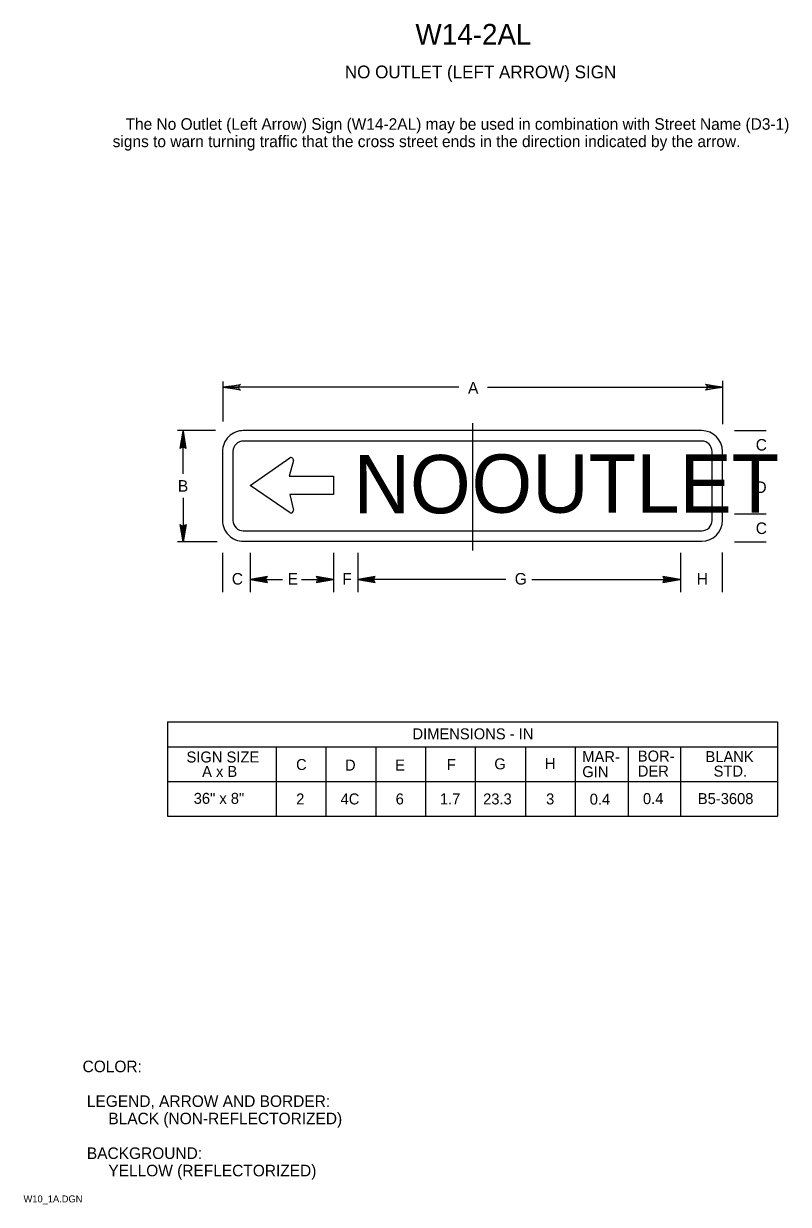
# Model space of a CAD drawing. Extents: x 0.013 to 0.178, y 0.004 to 0.259.
import ezdxf

# ---------------------------------------------------------------- set-up
doc = ezdxf.new("R2010")
doc.units = 0
for name, color, linetype in [('1', 7, 'Continuous'), ('2', 7, 'Continuous'), ('3', 7, 'Continuous')]:
    doc.layers.add(name, color=color, linetype=linetype)

# ---------------------------------------------------------------- blocks, each defined once
blk = doc.blocks.new('RARROW')
at = {"layer": '3'}
for p, q in [((-2.156, 0.28500000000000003), (-2.2665, 0.384625)), ((-2.2665, 0.384625), (0, 0)), ((0, 0), (-2.2665, -0.379125)), ((-2.156, 0.28500000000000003), (-2.075625, 0.12075)), ((0, 0), (-2.156, 0.28500000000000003)), ((-2.14975, -0.2705), (0, 0)), ((-2.075625, 0.12075), (0, 0)), ((0, 0), (-2.074, -0.108)), ((-2.2665, -0.379125), (-2.14975, -0.2705)), ((-2.074, -0.108), (-2.14975, -0.2705))]:
    blk.add_line(p, q, dxfattribs=at)

msp = doc.modelspace()

# ---------------------------------------------------------------- linework, layer by layer
at = {"layer": '1'}
msp.add_line((0.10961895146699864, 0.17275000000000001), (0.10961895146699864, 0.14523299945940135), dxfattribs=at)
at = {"layer": '3'}
for p, q in [((0.055725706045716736, 0.173125), (0.055725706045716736, 0.18174713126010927)), ((0.16373811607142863, 0.1725172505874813), (0.16373811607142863, 0.18188938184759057)), ((0.1066937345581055, 0.18049713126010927), (0.05576086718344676, 0.18049713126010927)), ((0.11287659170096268, 0.18049713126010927), (0.16372946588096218, 0.18049713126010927)), ((0.05409428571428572, 0.17112213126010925), (0.04588586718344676, 0.17112213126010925)), ((0.04713586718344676, 0.16175542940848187), (0.04713586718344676, 0.17112213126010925)), ((0.15914361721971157, 0.171125), (0.06009428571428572, 0.171125)), ((0.16620796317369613, 0.171125), (0.17308296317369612, 0.171125)), ((0.15914361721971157, 0.168875), (0.06009428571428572, 0.168875)), ((0.05559428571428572, 0.166625), (0.05559428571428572, 0.15172487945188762)), ((0.057844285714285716, 0.166625), (0.057844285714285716, 0.15172487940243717)), ((0.16139361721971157, 0.15172874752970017), (0.16139361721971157, 0.16662886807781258)), ((0.16364361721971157, 0.15172874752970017), (0.16364361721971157, 0.16662886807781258)), ((0.06159228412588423, 0.15924376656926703), (0.07016160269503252, 0.16523741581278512)), ((0.07091637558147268, 0.16466019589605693), (0.07003009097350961, 0.16127193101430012)), ((0.16620796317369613, 0.165125), (0.17308296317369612, 0.165125)), ((0.07003009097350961, 0.16127193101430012), (0.07958125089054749, 0.16127193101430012)), ((0.07958125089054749, 0.1612719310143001), (0.07958125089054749, 0.15730317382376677)), ((0.07020559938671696, 0.1533827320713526), (0.06159228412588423, 0.15924376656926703)), ((0.04713586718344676, 0.15662658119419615), (0.04713586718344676, 0.14722201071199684)), ((0.07958125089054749, 0.1573031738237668), (0.07013421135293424, 0.15730382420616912)), ((0.07013421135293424, 0.15730382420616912), (0.07091601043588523, 0.15391550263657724)), ((0.16620796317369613, 0.153125), (0.17308296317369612, 0.153125)), ((0.06009428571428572, 0.1494748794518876), (0.15914361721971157, 0.1494748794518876)), ((0.05446928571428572, 0.14712213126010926), (0.04588586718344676, 0.14712213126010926)), ((0.05446928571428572, 0.14712213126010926), (0.04588586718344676, 0.14712213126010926)), ((0.06009428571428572, 0.14722487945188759), (0.15914361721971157, 0.14722487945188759)), ((0.16620796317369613, 0.147125), (0.17308296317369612, 0.147125)), ((0.05559428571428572, 0.1447301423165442), (0.05559428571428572, 0.13619902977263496)), ((0.06159428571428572, 0.1447301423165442), (0.06159428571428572, 0.13619902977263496)), ((0.07959428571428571, 0.1447301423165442), (0.07959428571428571, 0.13619902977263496)), ((0.08484428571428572, 0.1447301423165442), (0.08484428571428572, 0.13619902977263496)), ((0.1545942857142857, 0.1447301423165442), (0.1545942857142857, 0.13619902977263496)), ((0.16359790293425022, 0.14478244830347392), (0.16359790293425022, 0.13619902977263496)), ((0.06159428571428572, 0.13896441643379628), (0.06858988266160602, 0.13896441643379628)), ((0.07268131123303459, 0.13896441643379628), (0.07959428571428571, 0.13896441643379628)), ((0.11683845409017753, 0.13896441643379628), (0.08484428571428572, 0.13896441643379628)), ((0.1224384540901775, 0.13896441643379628), (0.1545675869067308, 0.13896441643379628)), ((0.043705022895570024, 0.10817070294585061), (0.17553288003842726, 0.10817070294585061)), ((0.043705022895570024, 0.10817070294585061), (0.043705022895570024, 0.08779570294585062)), ((0.17553288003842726, 0.10817070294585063), (0.17553288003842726, 0.08779570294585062)), ((0.043705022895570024, 0.10279570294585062), (0.17553288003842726, 0.10279570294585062)), ((0.06720502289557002, 0.10279570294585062), (0.06720502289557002, 0.08779570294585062)), ((0.07795502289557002, 0.10279570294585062), (0.07795502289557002, 0.08779570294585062)), ((0.08870502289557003, 0.10279570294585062), (0.08870502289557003, 0.08779570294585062)), ((0.09945502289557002, 0.10279570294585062), (0.09945502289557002, 0.08779570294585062)), ((0.11020502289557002, 0.10279570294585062), (0.11020502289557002, 0.08779570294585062)), ((0.12108002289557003, 0.10279570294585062), (0.12108002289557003, 0.08779570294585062)), ((0.13183002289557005, 0.10279570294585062), (0.13183002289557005, 0.08779570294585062)), ((0.14326428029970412, 0.10279570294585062), (0.14326428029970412, 0.08779570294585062)), ((0.1545968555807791, 0.10279570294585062), (0.1545968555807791, 0.08779570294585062)), ((0.043705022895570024, 0.09529570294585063), (0.17553288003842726, 0.09529570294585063)), ((0.043705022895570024, 0.08779570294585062), (0.17553288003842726, 0.08779570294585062))]:
    msp.add_line(p, q, dxfattribs=at)
for centre, radius, start, end in [((0.06012654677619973, 0.1665966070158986), 0.004532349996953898, 89.64106666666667, 179.6410666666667), ((0.15914361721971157, 0.1666288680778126), 0.0045000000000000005, 0, 90), ((0.06012654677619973, 0.1665966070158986), 0.0022824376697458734, 89.28723611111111, 179.2872361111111), ((0.15914361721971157, 0.1666288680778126), 0.0022500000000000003, 0, 90), ((0.07041328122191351, 0.16478438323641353), 0.0005181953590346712, 346.1339084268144, 120.16766953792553), ((0.07044820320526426, 0.15380231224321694), 0.00048130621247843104, 239.54676398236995, 13.60184176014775), ((0.06012267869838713, 0.1517571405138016), 0.004528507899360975, 180.4081777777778, 270.40817777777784), ((0.06012267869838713, 0.1517571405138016), 0.002278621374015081, 180.81123055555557, 270.81123055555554), ((0.15914361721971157, 0.15172874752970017), 0.0045000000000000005, 270, 0), ((0.15914361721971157, 0.15172874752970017), 0.0022500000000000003, 270, 0)]:
    msp.add_arc(centre, radius, start, end, dxfattribs=at)

# ---------------------------------------------------------------- block references
at = {"layer": '3', "xscale": 0.0016545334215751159}
for p, yscale in [((0.16373033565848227, 0.1805172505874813), 0.0016366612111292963), ((0.07960074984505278, 0.13896728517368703), -0.0016366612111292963), ((0.15448416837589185, 0.13896728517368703), -0.0016366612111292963)]:
    msp.add_blockref('RARROW', p, dxfattribs=dict(at, yscale=yscale))
for p, yscale, rotation in [((0.05571928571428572, 0.1805), 0.0016366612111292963, 180), ((0.04709428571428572, 0.171), 0.0016366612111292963, 90), ((0.04709428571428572, 0.14709987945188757), 0.0016366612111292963, -90), ((0.06159428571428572, 0.13896441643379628), -0.0016366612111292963, 180), ((0.08484428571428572, 0.13896441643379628), -0.0016366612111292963, 180)]:
    msp.add_blockref('RARROW', p, dxfattribs=dict(at, yscale=yscale, rotation=rotation))

# ---------------------------------------------------------------- texts
at = {"layer": '1'}
for s, height, p in [('W14-2A', 0.0045000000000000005, (0.0972959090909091, 0.2545)), ('L', 0.0045000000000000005, (0.11897090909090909, 0.2545)), ('NO OUTLET (LEFT ARROW) SIGN', 0.00275025, (0.08204606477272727, 0.24725)), ('COLOR:', 0.0024997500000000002, (0.025375, 0.032499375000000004)), (' LEGEND, ARROW AND BORDER:', 0.0024997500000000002, (0.025375, 0.024999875)), ('      BLACK (NON-REFLECTORIZED)', 0.0024997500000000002, (0.025375, 0.021250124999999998)), (' BACKGROUND:', 0.0024997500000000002, (0.025375, 0.013750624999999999)), ('      YELLOW (REFLECTORIZED)', 0.0024997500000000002, (0.025375, 0.010000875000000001)), ('W10_1A.DGN', 0.0015, (0.012625, 0.004375))]:
    msp.add_text(s, height=height, dxfattribs=at).set_placement(p)
at = {"layer": '2'}
for s, p in [('   The No Outlet (Left Arrow) Sign (W14-2AL) may be used in combination with Street Name (D3-1) ', (0.03187847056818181, 0.23612525)), ('signs to warn turning traffic that the cross street ends in the direction indicated by the arrow.', (0.03187847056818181, 0.23237549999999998))]:
    msp.add_text(s, height=0.0024997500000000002, dxfattribs=at).set_placement(p)
at = {"layer": '3'}
for s, height, p in [('A', 0.0024997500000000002, (0.10866298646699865, 0.179125)), ('C', 0.0024997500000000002, (0.17083296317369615, 0.16681080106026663)), ('NO', 0.0126, (0.08396141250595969, 0.15326217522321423)), ('OUTLET', 0.0126, (0.1094256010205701, 0.15338666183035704)), ('B', 0.0024997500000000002, (0.04596928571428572, 0.1579250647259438)), ('D', 0.0024997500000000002, (0.17076137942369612, 0.15764858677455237)), ('C', 0.0024997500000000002, (0.17083296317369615, 0.14878514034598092)), ('C', 0.0024997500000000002, (0.057619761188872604, 0.13785942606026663)), ('E', 0.0024997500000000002, (0.06970952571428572, 0.13785942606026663)), ('F', 0.0024997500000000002, (0.08148549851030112, 0.13785942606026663)), ('G', 0.0024997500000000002, (0.11875157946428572, 0.13785942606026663)), ('H', 0.0024997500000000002, (0.15808108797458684, 0.13785942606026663)), ('DIMENSIONS - IN', 0.0023752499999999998, (0.09666124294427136, 0.10442070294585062)), ('SIGN SIZE', 0.0023752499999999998, (0.04783002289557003, 0.09942070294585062)), ('C', 0.0023752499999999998, (0.07150814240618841, 0.09779570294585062)), ('D', 0.0023752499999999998, (0.08208002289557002, 0.09767070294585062)), ('E', 0.0023752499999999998, (0.09290002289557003, 0.09767070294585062)), ('F', 0.0023752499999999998, (0.10408002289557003, 0.09779570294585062)), ('G', 0.0023752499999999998, (0.11434288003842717, 0.09793421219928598)), ('H', 0.0023752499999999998, (0.1252581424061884, 0.09802418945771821)), ('MAR-', 0.0023752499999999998, (0.13334707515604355, 0.09949533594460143)), ('BOR-', 0.0023752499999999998, (0.14534707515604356, 0.09962033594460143)), ('BLANK', 0.0023752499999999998, (0.1599720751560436, 0.09949533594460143)), ('A x B', 0.0023752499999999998, (0.051205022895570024, 0.09629570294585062)), ('GIN', 0.0023752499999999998, (0.13334707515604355, 0.09624533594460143)), ('DER', 0.0023752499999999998, (0.14534707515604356, 0.09637033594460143)), ('STD.', 0.0023752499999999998, (0.16172207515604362, 0.09637033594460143)), ('36" x 8"', 0.0023752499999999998, (0.049386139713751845, 0.09048307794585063)), ('2', 0.0023752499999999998, (0.07152855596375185, 0.09035807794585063)), ('4C', 0.0023752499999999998, (0.08111960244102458, 0.09035807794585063)), ('6', 0.0023752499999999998, (0.0930242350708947, 0.09035807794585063)), ('1.7', 0.0023752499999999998, (0.10257509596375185, 0.09035807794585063)), ('23.3', 0.0023752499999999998, (0.11192237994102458, 0.09035807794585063)), ('3', 0.0023752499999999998, (0.12552521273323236, 0.09035807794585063)), ('0.4', 0.0023752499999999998, (0.13495407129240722, 0.09030771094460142)), ('0.4', 0.0023752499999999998, (0.1464540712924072, 0.09043271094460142)), ('B5-3608', 0.0023752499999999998, (0.15831650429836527, 0.09043271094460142))]:
    msp.add_text(s, height=height, dxfattribs=at).set_placement(p)

doc.saveas('drawing.dxf')
